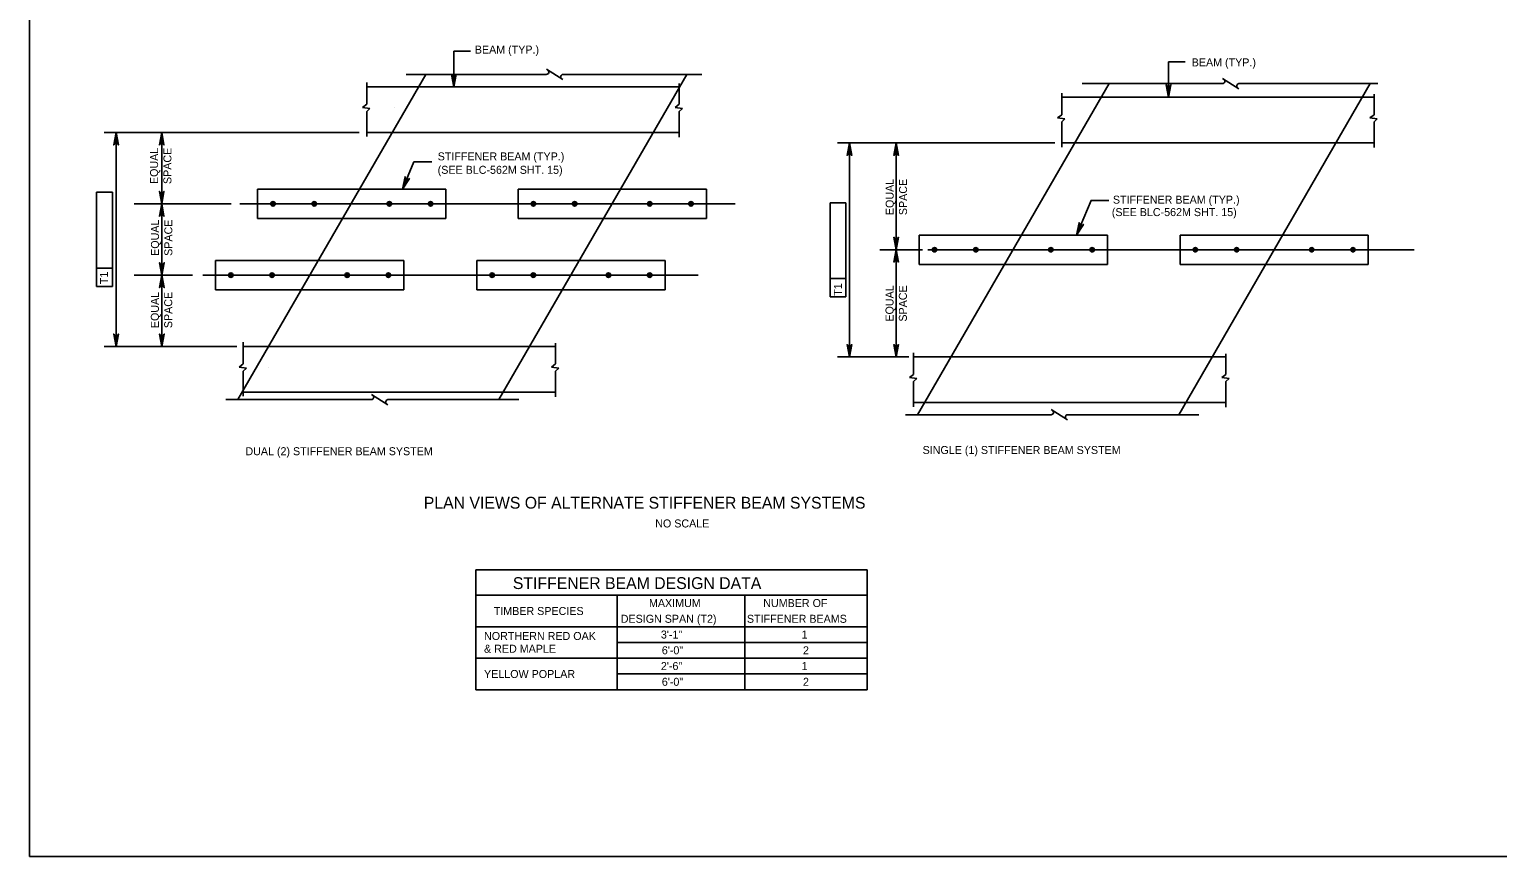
# Model space of a CAD drawing. Extents: x 638263 to 640391, y 293683 to 298655.
# Drawn here: x 639316 to 639867, y 296074 to 296385 of the extents above; entities that cross this region are included whole.
import ezdxf

# ---------------------------------------------------------------- set-up
doc = ezdxf.new("R2010")
doc.units = 0
for name, color, linetype in [('10', 7, 'Continuous'), ('2', 7, 'Continuous'), ('3', 7, 'Continuous'), ('4', 7, 'Continuous'), ('8', 7, 'Continuous')]:
    doc.layers.add(name, color=color, linetype=linetype)

msp = doc.modelspace()

# ---------------------------------------------------------------- linework, layer by layer
at = {"layer": '10'}
for p, q in [((639483.83, 296182.02), (639483.83, 296137.05)), ((639483.83, 296182.02), (639630.48, 296182.02)), ((639630.48, 296182.02), (639630.48, 296137.05)), ((639483.83, 296172.48), (639630.48, 296172.48)), ((639536.81, 296172.48), (639536.81, 296137.05)), ((639584.58, 296172.48), (639584.58, 296137.05)), ((639483.83, 296160.67), (639630.48, 296160.67)), ((639536.81, 296154.76), (639630.48, 296154.76)), ((639483.83, 296148.86), (639630.48, 296148.86)), ((639536.81, 296142.95), (639630.48, 296142.95)), ((639483.83, 296137.05), (639630.48, 296137.05))]:
    msp.add_line(p, q, dxfattribs=at)
at = {"layer": '2'}
for p, q in [((639316.46, 296074.46), (639316.46, 296638.46)), ((639465.09, 296367.77), (639394.6, 296245.82)), ((639562.92, 296367.77), (639492.43, 296245.82)), ((639721.15, 296364.35), (639649.36, 296240.17)), ((639818.98, 296364.35), (639747.2, 296240.17)), ((640102.46, 296074.46), (639316.46, 296074.46))]:
    msp.add_line(p, q, dxfattribs=at)
at = {"layer": '3'}
for p, q in [((639442.9, 296356.6), (639442.9, 296364.7)), ((639457.67, 296367.77), (639510.2, 296367.77)), ((639510.27, 296369.7), (639516.43, 296365.83)), ((639516.42, 296367.77), (639568.49, 296367.77)), ((639763.63, 296366.29), (639769.79, 296362.42)), ((639442.9, 296363.14), (639559.97, 296363.14)), ((639559.97, 296356.6), (639559.97, 296364.33)), ((639703.34, 296352.68), (639703.34, 296360.78)), ((639703.34, 296359.22), (639820.41, 296359.22)), ((639711.02, 296364.35), (639763.56, 296364.35)), ((639769.78, 296364.35), (639821.85, 296364.35)), ((639820.41, 296352.68), (639820.41, 296360.41)), ((639441.36, 296355.41), (639442.9, 296356.6)), ((639444.11, 296354.99), (639441.36, 296355.41)), ((639442.9, 296353.9), (639444.11, 296354.99)), ((639442.9, 296344.47), (639442.9, 296353.9)), ((639558.43, 296355.41), (639559.97, 296356.6)), ((639561.19, 296354.99), (639558.43, 296355.41)), ((639559.97, 296353.9), (639561.19, 296354.99)), ((639559.97, 296344.28), (639559.97, 296353.9)), ((639701.8, 296351.49), (639703.34, 296352.68)), ((639704.55, 296351.07), (639701.8, 296351.49)), ((639703.34, 296349.97), (639704.55, 296351.07)), ((639703.34, 296340.55), (639703.34, 296349.97)), ((639818.87, 296351.49), (639820.41, 296352.68)), ((639821.63, 296351.07), (639818.87, 296351.49)), ((639820.41, 296349.97), (639821.63, 296351.07)), ((639820.41, 296340.36), (639820.41, 296349.97)), ((639559.97, 296346.01), (639442.9, 296346.01)), ((639820.41, 296342.09), (639703.34, 296342.09)), ((639402.01, 296324.74), (639402.01, 296313.72)), ((639402.01, 296324.74), (639472.59, 296324.74)), ((639472.59, 296324.74), (639472.59, 296313.72)), ((639499.6, 296324.74), (639570.17, 296324.74)), ((639499.6, 296324.74), (639499.6, 296313.72)), ((639570.17, 296324.74), (639570.17, 296313.72)), ((639437.21, 296319.26), (639437.21, 296319.26)), ((639402.01, 296313.72), (639472.59, 296313.72)), ((639499.6, 296313.72), (639570.17, 296313.72)), ((639649.94, 296307.54), (639720.51, 296307.54)), ((639649.94, 296307.54), (639649.94, 296296.52)), ((639720.51, 296307.54), (639720.51, 296296.52)), ((639747.69, 296307.54), (639747.69, 296296.52)), ((639747.69, 296307.54), (639818.26, 296307.54)), ((639818.26, 296307.54), (639818.26, 296296.52)), ((639386.2, 296297.99), (639456.77, 296297.99)), ((639386.2, 296297.99), (639386.2, 296286.97)), ((639456.77, 296297.99), (639456.77, 296286.97)), ((639484.12, 296297.99), (639554.69, 296297.99)), ((639484.12, 296297.99), (639484.12, 296286.97)), ((639554.69, 296297.99), (639554.69, 296286.97)), ((639649.94, 296296.52), (639720.51, 296296.52)), ((639747.69, 296296.52), (639818.26, 296296.52)), ((639421.4, 296292.51), (639421.4, 296292.51)), ((639386.2, 296286.97), (639456.77, 296286.97)), ((639484.12, 296286.97), (639554.69, 296286.97)), ((639396.63, 296259.22), (639396.63, 296267.32)), ((639396.63, 296265.76), (639513.7, 296265.76)), ((639513.7, 296259.22), (639513.7, 296266.94)), ((639647.83, 296255.3), (639647.83, 296263.4)), ((639647.83, 296261.84), (639764.9, 296261.84)), ((639764.9, 296255.3), (639764.9, 296263.02)), ((639395.09, 296258.03), (639396.63, 296259.22)), ((639397.85, 296257.61), (639395.09, 296258.03)), ((639396.63, 296256.51), (639397.85, 296257.61)), ((639396.63, 296247.09), (639396.63, 296256.51)), ((639512.16, 296258.03), (639513.7, 296259.22)), ((639514.92, 296257.61), (639512.16, 296258.03)), ((639513.7, 296256.51), (639514.92, 296257.61)), ((639513.7, 296246.9), (639513.7, 296256.51)), ((639646.29, 296254.11), (639647.83, 296255.3)), ((639763.36, 296254.11), (639764.9, 296255.3)), ((639649.04, 296253.69), (639646.29, 296254.11)), ((639647.83, 296252.59), (639649.04, 296253.69)), ((639647.83, 296243.17), (639647.83, 296252.59)), ((639766.12, 296253.69), (639763.36, 296254.11)), ((639764.9, 296252.59), (639766.12, 296253.69)), ((639764.9, 296242.98), (639764.9, 296252.59)), ((639390.11, 296245.82), (639444.59, 296245.82)), ((639513.7, 296248.63), (639396.63, 296248.63)), ((639444.66, 296247.75), (639450.82, 296243.88)), ((639450.8, 296245.82), (639499.95, 296245.82)), ((639764.9, 296244.71), (639647.83, 296244.71)), ((639644.87, 296240.17), (639699.35, 296240.17)), ((639699.42, 296242.1), (639705.58, 296238.23)), ((639705.56, 296240.17), (639754.72, 296240.17))]:
    msp.add_line(p, q, dxfattribs=at)
for centre, radius in [((639407.77, 296319.23), 0.833), ((639407.77, 296319.23), 0.738), ((639407.77, 296319.23), 0.625), ((639407.77, 296319.23), 0.417), ((639407.77, 296319.23), 0.208), ((639423.22, 296319.23), 0.833), ((639423.22, 296319.23), 0.738), ((639423.22, 296319.23), 0.625), ((639423.22, 296319.23), 0.417), ((639423.22, 296319.23), 0.208), ((639451.37, 296319.23), 0.833), ((639451.37, 296319.23), 0.738), ((639451.37, 296319.23), 0.625), ((639451.37, 296319.23), 0.417), ((639451.37, 296319.23), 0.208), ((639466.83, 296319.23), 0.833), ((639466.83, 296319.23), 0.738), ((639466.83, 296319.23), 0.625), ((639466.83, 296319.23), 0.417), ((639466.83, 296319.23), 0.208), ((639505.36, 296319.23), 0.833), ((639505.36, 296319.23), 0.738), ((639505.36, 296319.23), 0.625), ((639505.36, 296319.23), 0.417), ((639505.36, 296319.23), 0.208), ((639520.81, 296319.23), 0.833), ((639520.81, 296319.23), 0.738), ((639520.81, 296319.23), 0.625), ((639520.81, 296319.23), 0.417), ((639520.81, 296319.23), 0.208), ((639548.96, 296319.23), 0.833), ((639548.96, 296319.23), 0.738), ((639548.96, 296319.23), 0.625), ((639548.96, 296319.23), 0.417), ((639548.96, 296319.23), 0.208), ((639564.41, 296319.23), 0.833), ((639564.41, 296319.23), 0.738), ((639564.41, 296319.23), 0.625), ((639564.41, 296319.23), 0.417), ((639564.41, 296319.23), 0.208), ((639655.7, 296302.03), 0.833), ((639655.7, 296302.03), 0.738), ((639655.7, 296302.03), 0.625), ((639655.7, 296302.03), 0.417), ((639655.7, 296302.03), 0.208), ((639671.15, 296302.03), 0.833), ((639671.15, 296302.03), 0.738), ((639671.15, 296302.03), 0.625), ((639671.15, 296302.03), 0.417), ((639671.15, 296302.03), 0.208), ((639699.3, 296302.03), 0.833), ((639699.3, 296302.03), 0.738), ((639699.3, 296302.03), 0.625), ((639699.3, 296302.03), 0.417), ((639699.3, 296302.03), 0.208), ((639714.75, 296302.03), 0.833), ((639714.75, 296302.03), 0.738), ((639714.75, 296302.03), 0.625), ((639714.75, 296302.03), 0.417), ((639714.75, 296302.03), 0.208), ((639753.44, 296302.03), 0.833), ((639753.44, 296302.03), 0.738), ((639753.44, 296302.03), 0.625), ((639753.44, 296302.03), 0.417), ((639753.44, 296302.03), 0.208), ((639768.9, 296302.03), 0.833), ((639768.9, 296302.03), 0.738), ((639768.9, 296302.03), 0.625), ((639768.9, 296302.03), 0.417), ((639768.9, 296302.03), 0.208), ((639797.05, 296302.03), 0.833), ((639797.05, 296302.03), 0.738), ((639797.05, 296302.03), 0.625), ((639797.05, 296302.03), 0.417), ((639797.05, 296302.03), 0.208), ((639812.5, 296302.03), 0.833), ((639812.5, 296302.03), 0.738), ((639812.5, 296302.03), 0.625), ((639812.5, 296302.03), 0.417), ((639812.5, 296302.03), 0.208), ((639391.96, 296292.48), 0.833), ((639391.96, 296292.48), 0.738), ((639391.96, 296292.48), 0.625), ((639407.41, 296292.48), 0.833), ((639407.41, 296292.48), 0.738), ((639407.41, 296292.48), 0.625), ((639435.56, 296292.48), 0.833), ((639435.56, 296292.48), 0.738), ((639435.56, 296292.48), 0.625), ((639451.02, 296292.48), 0.833), ((639451.02, 296292.48), 0.738), ((639451.02, 296292.48), 0.625), ((639489.88, 296292.48), 0.833), ((639489.88, 296292.48), 0.738), ((639489.88, 296292.48), 0.625), ((639505.33, 296292.48), 0.833), ((639505.33, 296292.48), 0.738), ((639505.33, 296292.48), 0.625), ((639533.48, 296292.48), 0.833), ((639533.48, 296292.48), 0.738), ((639533.48, 296292.48), 0.625), ((639548.93, 296292.48), 0.833), ((639548.93, 296292.48), 0.738), ((639548.93, 296292.48), 0.625), ((639391.96, 296292.48), 0.417), ((639391.96, 296292.48), 0.208), ((639407.41, 296292.48), 0.417), ((639407.41, 296292.48), 0.208), ((639435.56, 296292.48), 0.417), ((639435.56, 296292.48), 0.208), ((639451.02, 296292.48), 0.417), ((639451.02, 296292.48), 0.208), ((639489.88, 296292.48), 0.417), ((639489.88, 296292.48), 0.208), ((639505.33, 296292.48), 0.417), ((639505.33, 296292.48), 0.208), ((639533.48, 296292.48), 0.417), ((639533.48, 296292.48), 0.208), ((639548.93, 296292.48), 0.417), ((639548.93, 296292.48), 0.208)]:
    msp.add_circle(centre, radius, dxfattribs=at)
for centre, start, end in [((639510.2, 296368.68), 270, 60), ((639516.5, 296366.86), 95.3286, 237.8672), ((639763.56, 296365.26), 270, 60), ((639769.86, 296363.45), 95.3286, 237.8672), ((639444.59, 296246.73), 270, 60), ((639450.89, 296244.91), 95.3286, 237.8672), ((639699.35, 296241.07), 270, 60), ((639705.65, 296239.26), 95.3286, 237.8672)]:
    msp.add_arc(centre, 0.909, start, end, dxfattribs=at)
at = {"layer": '4'}
for p, q in [((639475.48, 296376.47), (639481.73, 296376.47)), ((639743.43, 296372.55), (639749.65, 296372.55)), ((639382.71, 296346.01), (639344.46, 296346.01)), ((639348.96, 296346.01), (639348.96, 296265.76)), ((639440.08, 296346.01), (639354.9, 296346.01)), ((639378.88, 296346.01), (639363.83, 296346.01)), ((639366.04, 296346.01), (639366.04, 296319.26)), ((639650.3, 296342.09), (639619.31, 296342.09)), ((639623.81, 296342.09), (639623.81, 296261.84)), ((639700.75, 296342.09), (639636.81, 296342.09)), ((639641.31, 296342.09), (639641.31, 296302.06)), ((639460.56, 296335.05), (639467.23, 296335.05)), ((639341.67, 296323.56), (639347.58, 296323.56)), ((639341.67, 296288.26), (639341.67, 296323.56)), ((639347.58, 296323.56), (639347.58, 296288.26)), ((639355.74, 296319.26), (639392.04, 296319.26)), ((639366.04, 296319.26), (639366.04, 296295.46)), ((639395.37, 296319.26), (639581.01, 296319.26)), ((639616.52, 296319.64), (639622.42, 296319.64)), ((639616.52, 296291.81), (639616.52, 296319.64)), ((639622.42, 296319.64), (639622.42, 296284.34)), ((639714.32, 296320.51), (639721.02, 296320.51)), ((639635.2, 296302.06), (639651.18, 296302.06)), ((639650.3, 296302.06), (639636.81, 296302.06)), ((639641.31, 296302.06), (639641.31, 296261.84)), ((639653.14, 296302.03), (639835.42, 296302.03)), ((639347.58, 296295.15), (639341.67, 296295.15)), ((639347.58, 296288.26), (639341.67, 296288.26)), ((639355.74, 296292.51), (639377.54, 296292.51)), ((639366.1, 296289.56), (639366.1, 296265.76)), ((639381.5, 296292.48), (639567.15, 296292.48)), ((639616.52, 296284.34), (639616.52, 296291.81)), ((639622.42, 296291.23), (639616.52, 296291.23)), ((639622.42, 296284.34), (639616.52, 296284.34)), ((639394.16, 296265.76), (639344.46, 296265.76)), ((639372.59, 296265.76), (639364.21, 296265.76)), ((639646, 296261.84), (639619.31, 296261.84))]:
    msp.add_line(p, q, dxfattribs=at)
for points in [[(639475.48, 296363.14), (639475.48, 296376.47)], [(639743.43, 296359.22), (639743.43, 296372.55)], [(639475.48, 296363.14), (639474.61, 296367.8), (639474.86, 296367.44), (639475.17, 296367.25), (639475.48, 296367.2), (639475.79, 296367.25), (639476.11, 296367.44), (639476.35, 296367.8), (639475.48, 296363.14), (639476.11, 296367.44), (639475.79, 296367.25), (639475.48, 296363.14), (639475.48, 296367.2), (639475.17, 296367.25), (639475.48, 296363.14), (639474.86, 296367.44)], [(639743.43, 296359.22), (639742.56, 296363.88), (639742.81, 296363.52), (639743.12, 296363.33), (639743.43, 296363.28), (639743.75, 296363.33), (639744.06, 296363.52), (639744.31, 296363.88), (639743.43, 296359.22), (639744.06, 296363.52), (639743.75, 296363.33), (639743.43, 296359.22), (639743.43, 296363.28), (639743.12, 296363.33), (639743.43, 296359.22), (639742.81, 296363.52)], [(639348.96, 296346.01), (639349.83, 296341.35), (639349.59, 296341.71), (639349.27, 296341.9), (639348.96, 296341.95), (639348.65, 296341.9), (639348.34, 296341.71), (639348.09, 296341.35), (639348.96, 296346.01), (639348.34, 296341.71), (639348.65, 296341.9), (639348.96, 296346.01), (639348.96, 296341.95), (639349.27, 296341.9), (639348.96, 296346.01), (639349.59, 296341.71)], [(639366.04, 296346.01), (639366.91, 296341.35), (639366.67, 296341.71), (639366.35, 296341.9), (639366.04, 296341.95), (639365.73, 296341.9), (639365.42, 296341.71), (639365.17, 296341.35), (639366.04, 296346.01), (639365.42, 296341.71), (639365.73, 296341.9), (639366.04, 296346.01), (639366.04, 296341.95), (639366.35, 296341.9), (639366.04, 296346.01), (639366.67, 296341.71)], [(639623.81, 296342.09), (639624.68, 296337.43), (639624.43, 296337.79), (639624.12, 296337.98), (639623.81, 296338.03), (639623.49, 296337.98), (639623.18, 296337.79), (639622.93, 296337.43), (639623.81, 296342.09), (639623.18, 296337.79), (639623.49, 296337.98), (639623.81, 296342.09), (639623.81, 296338.03), (639624.12, 296337.98), (639623.81, 296342.09), (639624.43, 296337.79)], [(639641.31, 296342.09), (639642.19, 296337.43), (639641.94, 296337.79), (639641.63, 296337.98), (639641.31, 296338.03), (639641, 296337.98), (639640.69, 296337.79), (639640.44, 296337.43), (639641.31, 296342.09), (639640.69, 296337.79), (639641, 296337.98), (639641.31, 296342.09), (639641.31, 296338.03), (639641.63, 296337.98), (639641.31, 296342.09), (639641.94, 296337.79)], [(639456.25, 296324.74), (639460.57, 296335.05)], [(639456.25, 296324.74), (639457.24, 296329.38), (639457.34, 296328.95), (639457.55, 296328.66), (639457.82, 296328.49), (639458.13, 296328.42), (639458.49, 296328.47), (639458.86, 296328.7), (639456.25, 296324.74), (639458.49, 296328.47), (639458.13, 296328.42), (639456.25, 296324.74), (639457.82, 296328.49), (639457.55, 296328.66), (639456.25, 296324.74), (639457.34, 296328.95)], [(639366.04, 296319.26), (639365.17, 296323.92), (639365.42, 296323.56), (639365.73, 296323.38), (639366.04, 296323.32), (639366.35, 296323.38), (639366.67, 296323.56), (639366.91, 296323.92), (639366.04, 296319.26), (639366.67, 296323.56), (639366.35, 296323.38), (639366.04, 296319.26), (639366.04, 296323.32), (639365.73, 296323.38), (639366.04, 296319.26), (639365.42, 296323.56)], [(639366.04, 296319.26), (639365.17, 296314.6), (639365.42, 296314.96), (639365.73, 296315.14), (639366.04, 296315.2), (639366.35, 296315.14), (639366.67, 296314.96), (639366.91, 296314.6), (639366.04, 296319.26), (639366.67, 296314.96), (639366.35, 296315.14), (639366.04, 296319.26), (639366.04, 296315.2), (639365.73, 296315.14), (639366.04, 296319.26), (639365.42, 296314.96)], [(639708.89, 296307.54), (639714.33, 296320.51)], [(639708.89, 296307.54), (639709.89, 296312.18), (639709.98, 296311.75), (639710.2, 296311.46), (639710.46, 296311.29), (639710.77, 296311.22), (639711.13, 296311.27), (639711.5, 296311.5), (639708.89, 296307.54), (639711.13, 296311.27), (639710.77, 296311.22), (639708.89, 296307.54), (639710.46, 296311.29), (639710.2, 296311.46), (639708.89, 296307.54), (639709.98, 296311.75)], [(639641.31, 296302.06), (639642.19, 296306.72), (639641.94, 296306.36), (639641.63, 296306.18), (639641.31, 296306.12), (639641, 296306.18), (639640.69, 296306.36), (639640.44, 296306.72), (639641.31, 296302.06), (639640.69, 296306.36), (639641, 296306.18), (639641.31, 296302.06), (639641.31, 296306.12), (639641.63, 296306.18), (639641.31, 296302.06), (639641.94, 296306.36)], [(639641.31, 296302.06), (639642.19, 296297.4), (639641.94, 296297.76), (639641.63, 296297.94), (639641.31, 296298), (639641, 296297.94), (639640.69, 296297.76), (639640.44, 296297.4), (639641.31, 296302.06), (639640.69, 296297.76), (639641, 296297.94), (639641.31, 296302.06), (639641.31, 296298), (639641.63, 296297.94), (639641.31, 296302.06), (639641.94, 296297.76)], [(639366.1, 296292.51), (639365.23, 296297.17), (639365.48, 296296.81), (639365.79, 296296.63), (639366.1, 296296.57), (639366.42, 296296.63), (639366.73, 296296.81), (639366.98, 296297.17), (639366.1, 296292.51), (639366.73, 296296.81), (639366.42, 296296.63), (639366.1, 296292.51), (639366.1, 296296.57), (639365.79, 296296.63), (639366.1, 296292.51), (639365.48, 296296.81)], [(639366.1, 296292.51), (639365.23, 296287.85), (639365.48, 296288.21), (639365.79, 296288.39), (639366.1, 296288.45), (639366.42, 296288.39), (639366.73, 296288.21), (639366.98, 296287.85), (639366.1, 296292.51), (639366.73, 296288.21), (639366.42, 296288.39), (639366.1, 296292.51), (639366.1, 296288.45), (639365.79, 296288.39), (639366.1, 296292.51), (639365.48, 296288.21)], [(639348.96, 296265.76), (639348.09, 296270.42), (639348.34, 296270.06), (639348.65, 296269.87), (639348.96, 296269.82), (639349.27, 296269.87), (639349.59, 296270.06), (639349.83, 296270.42), (639348.96, 296265.76), (639349.59, 296270.06), (639349.27, 296269.87), (639348.96, 296265.76), (639348.96, 296269.82), (639348.65, 296269.87), (639348.96, 296265.76), (639348.34, 296270.06)], [(639366.1, 296265.76), (639365.23, 296270.42), (639365.48, 296270.06), (639365.79, 296269.87), (639366.1, 296269.82), (639366.42, 296269.87), (639366.73, 296270.06), (639366.98, 296270.42), (639366.1, 296265.76), (639366.73, 296270.06), (639366.42, 296269.87), (639366.1, 296265.76), (639366.1, 296269.82), (639365.79, 296269.87), (639366.1, 296265.76), (639365.48, 296270.06)], [(639623.81, 296261.84), (639622.93, 296266.5), (639623.18, 296266.14), (639623.49, 296265.95), (639623.81, 296265.9), (639624.12, 296265.95), (639624.43, 296266.14), (639624.68, 296266.5), (639623.81, 296261.84), (639624.43, 296266.14), (639624.12, 296265.95), (639623.81, 296261.84), (639623.81, 296265.9), (639623.49, 296265.95), (639623.81, 296261.84), (639623.18, 296266.14)], [(639641.31, 296261.84), (639640.44, 296266.5), (639640.69, 296266.14), (639641, 296265.95), (639641.31, 296265.9), (639641.63, 296265.95), (639641.94, 296266.14), (639642.19, 296266.5), (639641.31, 296261.84), (639641.94, 296266.14), (639641.63, 296265.95), (639641.31, 296261.84), (639641.31, 296265.9), (639641, 296265.95), (639641.31, 296261.84), (639640.69, 296266.14)]]:
    msp.add_lwpolyline(points, dxfattribs=at)
for points in [[(639475.48, 296363.14), (639475.51, 296363.26), (639475.45, 296363.26)], [(639743.43, 296359.22), (639743.46, 296359.33), (639743.4, 296359.33)], [(639623.31, 296339.09), (639624.31, 296339.09), (639623.81, 296342.09)], [(639640.81, 296339.09), (639641.81, 296339.09), (639641.31, 296342.09)], [(639456.25, 296324.74), (639456.32, 296324.84), (639456.27, 296324.86)], [(639640.81, 296305.06), (639641.81, 296305.06), (639641.31, 296302.06)], [(639708.89, 296307.54), (639708.97, 296307.64), (639708.91, 296307.66)], [(639640.81, 296299.06), (639641.81, 296299.06), (639641.31, 296302.06)], [(639365.55, 296295.46), (639366.53, 296295.46), (639366.04, 296292.51)], [(639365.61, 296289.56), (639366.6, 296289.56), (639366.1, 296292.51)], [(639348.46, 296268.76), (639349.46, 296268.76), (639348.96, 296265.76)], [(639365.61, 296268.71), (639366.6, 296268.71), (639366.1, 296265.76)], [(639623.31, 296264.84), (639624.31, 296264.84), (639623.81, 296261.84)], [(639640.81, 296265.03), (639641.81, 296265.03), (639641.31, 296262.03)]]:
    msp.add_lwpolyline(points, close=True, dxfattribs=at)
at = {"layer": '8'}
for p, q in [((639453.17, 296355.24), (639453.17, 296355.24)), ((639453.19, 296355.27), (639453.19, 296355.27)), ((639437.21, 296319.26), (639437.21, 296319.26)), ((639421.4, 296292.51), (639421.4, 296292.51)), ((639406.12, 296257.86), (639406.12, 296257.86))]:
    msp.add_line(p, q, dxfattribs=at)

# ---------------------------------------------------------------- texts
at = {"layer": '4'}
for s, height, p in [('BEAM (TYP.)', 3, (639483.4, 296375.57)), ('BEAM (TYP.)', 3, (639752.08, 296370.79)), ('STIFFENER BEAM (TYP.)', 3, (639469.48, 296335.54)), ('(SEE BLC-562M SHT. 15)', 3, (639469.48, 296330.5)), ('STIFFENER BEAM (TYP.)', 3, (639722.54, 296319.3)), ('(SEE BLC-562M SHT. 15)', 3, (639722.13, 296314.65)), ('DUAL (2) STIFFENER BEAM SYSTEM', 3, (639397.42, 296224.98)), ('SINGLE (1) STIFFENER BEAM SYSTEM', 3, (639651.22, 296225.43)), ('PLAN VIEWS OF ALTERNATE STIFFENER BEAM SYSTEMS', 4.4292, (639464.27, 296204.95)), ('NO SCALE', 3, (639551.01, 296197.9)), ('STIFFENER BEAM DESIGN DATA', 4.4292, (639497.65, 296174.81)), ('TIMBER SPECIES', 3, (639490.5, 296165.07)), ('MAXIMUM', 3, (639548.67, 296168.05)), ('NUMBER OF ', 3, (639591.5, 296168.05)), ('DESIGN SPAN (T2)', 3, (639538.09, 296162.15)), ('STIFFENER BEAMS', 3, (639585.37, 296162.15)), ('NORTHERN RED OAK', 3, (639486.86, 296155.7)), ('3\'-1"', 3, (639553.14, 296156.24)), ('1', 3, (639605.86, 296156.24)), ('& RED MAPLE', 3, (639486.86, 296150.92)), ('6\'-0"', 3, (639553.49, 296150.34)), ('2', 3, (639606.38, 296150.34)), ('YELLOW POPLAR', 3, (639486.86, 296141.45)), ('2\'-6"', 3, (639553.14, 296144.43)), ('1', 3, (639605.86, 296144.43)), ('6\'-0"', 3, (639553.49, 296138.52)), ('2', 3, (639606.38, 296138.52))]:
    msp.add_text(s, height=height, dxfattribs=at).set_placement(p)
for p in [(639345.92, 296289.14), (639620.99, 296284.77)]:
    msp.add_text('T1', height=3, rotation=90, dxfattribs=at).set_placement(p)
at = {"layer": '8'}
for s, p in [('EQUAL ', (639364.69, 296326.67)), ('SPACE', (639369.69, 296326.67)), ('EQUAL ', (639640.38, 296315.02)), ('SPACE', (639645.38, 296315.01)), ('EQUAL ', (639365.03, 296299.74)), ('SPACE', (639370.03, 296299.74)), ('EQUAL ', (639640.32, 296275.08)), ('SPACE', (639645.32, 296275.08)), ('EQUAL ', (639364.99, 296272.63)), ('SPACE', (639369.99, 296272.63))]:
    msp.add_text(s, height=3, rotation=89.9708, dxfattribs=at).set_placement(p)

doc.saveas('drawing.dxf')
